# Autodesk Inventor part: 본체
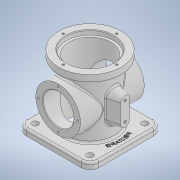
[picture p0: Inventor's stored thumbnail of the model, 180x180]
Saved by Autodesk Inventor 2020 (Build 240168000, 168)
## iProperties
Created: 2021-03
Part Number: 본체
Material: 일반
Document SubType Name: Modeling
Designer: USER
Density: 1 g/cm^3
Appearance: 기본값
Author: USER
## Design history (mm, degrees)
sketch "스케치1"
  geometry: L1 (57, -57)-(-57, -57); L2 (-57, -57)-(-57, 57); L3 (-57, 57)-(57, 57); L4 (57, 57)-(57, -57); L5 (57, -57)-(-57, 57); L6 (-57, -57)-(57, 57); 1 further point
  constraints: 12 end point, 2 midpoint, 2 parallel, 1 horizontal, 1 perpendicular
  dimensions: "d0" = 114 distance of L1.start L1.end; "d1" = 114 distance of L1.end L2.end
extrude "돌출1" new body sketch "스케치1" distance "d2" = 10; taper "d3" = 0 deg
sketch "스케치2"
  geometry: C1 r 38 at (0, 0); 1 further point
  constraints: 1 centre point, 1 coincident
  dimensions: "d4" = 76 diameter of C1
extrude "돌출2" join sketch "스케치2" distance "d5" = 101; taper "d6" = 0 deg
sketch "스케치3"
  geometry: C1 r 49 at (0, 0); 1 further point
  constraints: 1 centre point, 1 coincident
  dimensions: "d7" = 98 diameter of C1
extrude "돌출3" join sketch "스케치3" distance "d8" = 13; taper "d9" = 0 deg
sketch "스케치4"
  geometry: L1 (57, 0)-(-57, 0) reference; C1 r 35 at (0, 54); 2 further points
  constraints: 1 centre point, 1 midpoint, 1 vertical alignment
  dimensions: "d10" = 54 distance from line of C1.centre L1; "d11" = 70 diameter of C1
extrude "돌출4" join sketch "스케치4" stored distance "d12" = 100; taper "d13" = 0 deg
sketch "스케치5"
  geometry: C1 r 38 at (0, 0) reference; 2 further points
  constraints: 1 coincident
hole "구멍1" sketch "스케치5" at (0, 0) diameter "d14" = 66; stored, may be unused: countersink angle "d18" = 90 deg, drill point angle "d20" = 118 deg; dims "d15" = 6, "d16" = 74, "d17" = 7, "d19" = 8
sketch "스케치6"
  geometry: C1 r 35 at (0, 0) reference; 2 further points
  constraints: 1 coincident
hole "구멍2" sketch "스케치6" at (0, 0) diameter "d21" = 48; stored, may be unused: countersink angle "d25" = 90 deg, drill point angle "d27" = 118 deg; dims "d22" = 6, "d23" = 74, "d24" = 7, "d26" = 8
sketch "스케치7" dims "d28" = 62
  geometry: C1 r 35 at (0, 0) reference; 3 further points
  constraints: 2 vertical alignment, 1 coincident, 2 other
hole "구멍3" sketch "스케치7" at (0, 31) diameter "d29" = 3.242; stored, may be unused: countersink angle "d33" = 90 deg, drill point angle "d35" = 118 deg; dims "d30" = 6, "d31" = 74, "d32" = 7, "d34" = 8
sketch "스케치8" dims "d39" = 84
  geometry: C1 r 49 at (0, 0) reference; 3 further points
  constraints: 2 horizontal alignment, 1 coincident, 2 other
hole "구멍4" sketch "스케치8" at (-42, 0) diameter "d40" = 3.242; stored, may be unused: countersink angle "d44" = 90 deg, drill point angle "d46" = 118 deg; dims "d41" = 6, "d42" = 74, "d43" = 7, "d45" = 8
fillet "모깎기1" dims "d50" = 14
sketch "스케치9"
  geometry: A1 r 14 centre (-43, -43) between (-57, -43) and (-43, -57) reference; A2 r 14 centre (-43, 43) between (-43, 57) and (-57, 43) reference; A3 r 14 centre (43, 43) between (57, 43) and (43, 57) reference; A4 r 14 centre (43, -43) between (43, -57) and (57, -43) reference; 5 further points
  constraints: 4 coincident
hole "구멍5" sketch "스케치9" at (-43, -43), (-43, 43), (43, 43), (43, -43) diameter "d51" = 10; stored, may be unused: countersink angle "d55" = 90 deg, drill point angle "d57" = 118 deg; dims "d52" = 6, "d53" = 74, "d54" = 7, "d56" = 8
node "작업 평면1"
sketch "스케치10"
  geometry: L1 (68.5, 0)-(39.5, 0); L2 (68.5, 7)-(39.5, 7); L3 (39.5, -7)-(68.5, -7); L4 (0, 43)-(0, -43) reference; L5 (0, 43)-(0, 57) reference; A1 r 7 centre (68.5, 0) between (68.5, -7) and (68.5, 7); A2 r 7 centre (39.5, 0) between (39.5, 7) and (39.5, -7); 3 further points
  constraints: 8 end point, 4 point on circle, 4 tangent, 2 centre point, 2 midpoint, 1 horizontal, 1 horizontal alignment, 1 parallel
  dimensions: "d60" = 14 distance between parallel lines of L3 L2; "d63" = 54 distance from line of L5 point (54, 0); "d64" = 43 dimension on A2 A1
extrude "돌출5" join sketch "스케치10" stored distance "d65" = 100; taper "d66" = 15 deg
sketch "스케치11"
  geometry: A1 r 7 centre (0, 68.5) between (7, 68.5) and (-7, 68.5) reference; A2 r 7 centre (0, 39.5) between (-7, 39.5) and (7, 39.5) reference; 3 further points
  constraints: 2 coincident
hole "구멍6" sketch "스케치11" at (0, 68.5), (0, 39.5) diameter "d67" = 4.134; stored, may be unused: countersink angle "d71" = 90 deg, drill point angle "d73" = 118 deg; dims "d68" = 8, "d69" = 74, "d70" = 7, "d72" = 10
chamfer "모따기1" distance "d74" = 1; stored, may be unused: second distance "d75" = 2, angle "d76" = 45 deg
chamfer "모따기2" distance "d77" = 1; stored, may be unused: second distance "d78" = 2, angle "d79" = 45 deg
fillet "모깎기2" dims "d80" = 3
sketch "스케치12"
  geometry: C1 r 33 at (0, 0) reference; C2 r 50 at (0, 0); 1 further point
  constraints: 1 centre point, 1 coincident, 1 other
  dimensions: "d81" = 100 diameter of C2
feature "엠보싱1" sketch "스케치12" dims "d0" = 114, "d1" = 114, "d10" = 54, "d11" = 70, "d82" = 0.5, "d83" = 0
node "솔리드1"
pattern_circular "원형 패턴1" dims angle "d37" = 360 deg
mirror "미러1"
pattern_circular "원형 패턴2" dims angle "d48" = 360 deg
feature "A9D066F2-1C7D-4E18-AEED-F7BC21143FA4" dims "d21" = 48, "d22" = 6, "d23" = 74, "d24" = 7, "d25" = 90 deg, "d26" = 8, "d27" = 118 deg
other parameters: "d58" = 55
